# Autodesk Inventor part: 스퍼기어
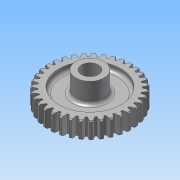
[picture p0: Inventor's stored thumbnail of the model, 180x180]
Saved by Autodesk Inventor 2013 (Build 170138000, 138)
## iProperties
Created: 2013-08
Part Number: 스퍼기어
Material: 강
Document SubType Name: Modeling
Designer: 한국산업디자인학원
Categories: <?xml version="1.0" encoding="UTF-16"?> <MemberInstance><Categories><FamilyTemplate><FamilyTemplateParameter ValueType="xs:double" Id="1" ObjectReferenceKey="da
Density: 1 g/cm^3
CustomPartVersion: 1
Author: 한국산업디자인학원
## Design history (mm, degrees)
sketch "Sketch1"
  geometry: C1 r 37 at (0, 0)
  constraints: 1 centre point
  dimensions: "d0" = 74 diameter of C1 (= da_da)
extrude "Extrusion1" new body sketch "Sketch1" distance "d1" = 15 (= da_b); taper "d2" = 0 deg
chamfer "모따기1" distance "d49" = 1; stored, may be unused: second distance "d50" = 2, angle "d51" = 45 deg
workplane "Work Plane2"
feature "피치 지름" dims "d4" = 10, "d5" = 0
workplane "Work Plane8"
workplane "Work Plane9"
feature "스퍼 기어" dims "da_b" = 15, "da_d" = 70, "da_aw" = 70, "da_da" = 74, "da_df" = 65, "da_dw" = 70, angle "da_beta" = 0 deg, "da_lefttooth" = 0, "da_righttooth" = 0
sketch "스케치3"
  geometry: C1 r 27.5 at (0, 0); A1 r 36 centre (0, 0) between (-5.215, 35.62) and (-7.633, 35.181) reference
  constraints: 1 centre point, 1 coincident
  dimensions: "d52" = 55 diameter of C1
extrude "돌출2" cut sketch "스케치3" distance "d54" = 5; taper "d55" = 0 deg
sketch "스케치4"
  geometry: C1 r 27.5 at (0, 0) reference
extrude "돌출3" cut sketch "스케치4" distance "d56" = 5; taper "d57" = 0 deg
sketch "스케치5"
  geometry: C1 r 27.5 at (0, 0) reference; C2 r 12.5 at (0, 0)
  constraints: 1 centre point, 1 coincident
  dimensions: "d58" = 25 diameter of C2
extrude "돌출4" join sketch "스케치5" distance "d60" = 8; taper "d61" = 0 deg
sketch "스케치6"
  geometry: C1 r 27.5 at (0, 0) reference; C2 r 12.5 at (0, 0)
  constraints: 1 centre point, 1 coincident
  dimensions: "d62" = 25 diameter of C2
extrude "돌출5" join sketch "스케치6" distance "d64" = 18; taper "d65" = 0 deg
hole "구멍1" diameter "d68" = 15; stored, may be unused: countersink angle "d72" = 90 deg, drill point angle "d74" = 118 deg; dims "d66" = 10, "d67" = 10, "d69" = 6, "d70" = 4, "d71" = 2, "d73" = 8
sketch "스케치7"
  geometry: L1 (-2.5, 7.071)-(-2.5, 9.8); L2 (-2.5, 9.8)-(2.5, 9.8); L3 (2.5, 9.8)-(2.5, 7.071); C1 r 12.5 at (0, 0) reference; A1 r 7.5 centre (0, 0) between (-2.5, 7.071) and (2.5, 7.071) reference
  constraints: 6 end point, 2 parallel, 2 point on circle, 1 perpendicular, 1 vertical
  dimensions: "d75" = 5 distance of L1.end L2.end; "d77" = 17.3 dimension on A1 L2
fillet "모깎기1" dims "d78" = 3
body "Solid1"
sketch "Sketch2"
  geometry: C1 r 37 at (0, 0) reference; C2 r 35 at (0, 0)
  constraints: 1 centre point, 1 coincident
  dimensions: "d3" = 70 diameter of C2 (= da_dw)
body "Srf1"
other parameters: "d17" = 0, "d34" = 0.8976 (computed from da_z), "d39" = 0, "d41" = 0, "d47" = 0, "d48" = 0
